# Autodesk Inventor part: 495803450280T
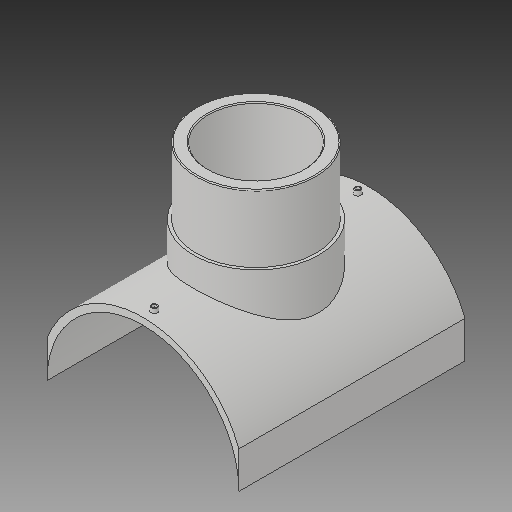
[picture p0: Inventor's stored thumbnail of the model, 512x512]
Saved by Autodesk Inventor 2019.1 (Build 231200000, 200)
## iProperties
Created: 2017-10
Part Number: 495803450280T
Material: Generic
Description: PLASSON BRANCH SADDLE  450x280
Document SubType Name: Modeling
Designer: KIM
Mass: 2754.05 g
Surface Area: 3037.44 cm^2
Volume: 2754.05 cm^3
Density: 1 g/cm^3
Appearance: Default
Author: KIM
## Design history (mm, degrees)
derived "495803.ipt"
feature "Solid1::495803.ipt"
tag "TaggingFeature1"
body "Solid1"
other parameters: "d1" = 16, "d4" = 0, "d12" = 250.6, "d13" = 14, "d14" = 238.5, "d16" = 5 deg, "d18" = 4, "d19" = 14, "d20" = 0, "d21" = 3, "d22" = 0, "d23" = 466, "d24" = 294, "d25" = 16, "d26" = 224, "d28" = 0, "d29" = 9.6, "d31" = 0, "d32" = 112.5, "d33" = 0, "d34" = 4.5, "d37" = 157.5, "d38" = 0, "d39" = 2.25, "H_" = 225, "x_" = 16, "D_" = 16
